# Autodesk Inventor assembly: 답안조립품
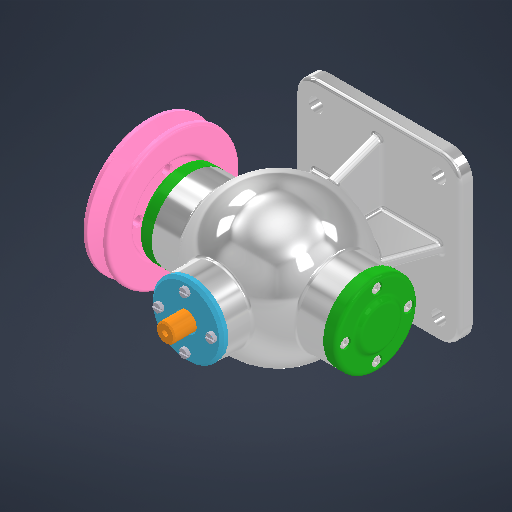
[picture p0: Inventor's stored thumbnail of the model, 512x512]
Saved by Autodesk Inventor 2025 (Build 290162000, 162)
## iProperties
Created: 2025-08
Part Number: 답안조립품
Document SubType Name: Assembly
Designer: infra027
Author: infra027
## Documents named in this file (15)
- C:\Users\infra027\Desktop\750807v1009\답안조립품.iam
- C:\Users\infra027\Desktop\750807v1009\본체.ipt
- C:\Users\infra027\Desktop\750807v1009\뒤커버\뒤커버.ipt
- C:\Users\infra027\Desktop\750807v1009\앞커버\앞커버.ipt
- C:\Users\infra027\Desktop\750807v1009\상부커버\상부커버.ipt
- C:\Users\infra027\Desktop\750807v1009\베어링- 6202\베어링- 6202.ipt
- C:\Users\infra027\Desktop\750807v1009\칼라\칼라.ipt
- C:\Users\infra027\Desktop\750807v1009\편심축\편심축.ipt
- C:\Users\infra027\Desktop\750807v1009\키 4 x 4 x 12\키 4 x 4 x 12.ipt
- C:\Users\infra027\Desktop\750807v1009\오일실 15 30 7\오일실 15 30 7.ipt
- C:\Users\infra027\Desktop\750807v1009\V-벨트풀리\V-벨트풀리.ipt
- C:\Users\infra027\Desktop\750807v1009\너트 M8\너트 M8.ipt
- C:\Users\infra027\Desktop\750807v1009\슬라이드\슬라이드.ipt
- C:\Users\infra027\Desktop\750807v1009\볼트 M4 x 16\볼트 M4 x 16.ipt
- C:\Users\infra027\Desktop\750807v1009\볼트 M4 x 12\볼트 M4 x 12.ipt
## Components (1 placed, 1 different names)
1. V-벨트풀리:1
